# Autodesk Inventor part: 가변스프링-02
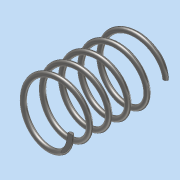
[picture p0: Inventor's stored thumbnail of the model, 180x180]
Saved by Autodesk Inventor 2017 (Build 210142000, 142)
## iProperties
Part Number: 가변스프링-02
Material: 강철, 연강
Document SubType Name: Modeling
Designer: MRC
Mass: 8.42563 g
Surface Area: 21.7273 cm^2
Volume: 1.07333 cm^3
Density: 7.85 g/cm^3
Appearance: 반연마
Author: MRC
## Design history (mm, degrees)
sketch "스케치1"
  geometry: L1 (0, 0)-(0, 37.411); L2 (0, 0)-(11, 0); L3 (0, 37.411)-(11, 37.411); C1 r 1 at (11, 0)
  constraints: 6 end point, 2 horizontal, 1 centre point, 1 coincident, 1 vertical
  dimensions: "d0" = 37.4112 distance of L1.start L1.end (derived); "d1" = 11 distance of L1.start L2.end; "d2" = 2 diameter of C1
feature "코일1" sketch "스케치1" pitch "d3" = 10; turns "d5" = 5; dims "d4" = 37.4112 (= d0), "d6" = 0, angle "d7" = 90 deg, angle "d8" = 90 deg, "d9" = 0, "d10" = 0
sketch "스케치2"
  geometry: L1 (37.411, 15)-(0, 15); L2 (0, 15)-(0, -15); L3 (0, -15)-(37.411, -15); L4 (37.411, -15)-(37.411, 15); 2 further points
  constraints: 8 end point, 2 parallel, 1 coincident, 1 horizontal, 1 midpoint, 1 perpendicular
  dimensions: "d11" = 37.4112 distance of L1.start L1.end (= d0); "d12" = 30 distance of L3.end L1.start
extrude "돌출1" sketch "스케치2" stored distance "d13" = 0; taper "d14" = 0 deg
node "솔리드1"
